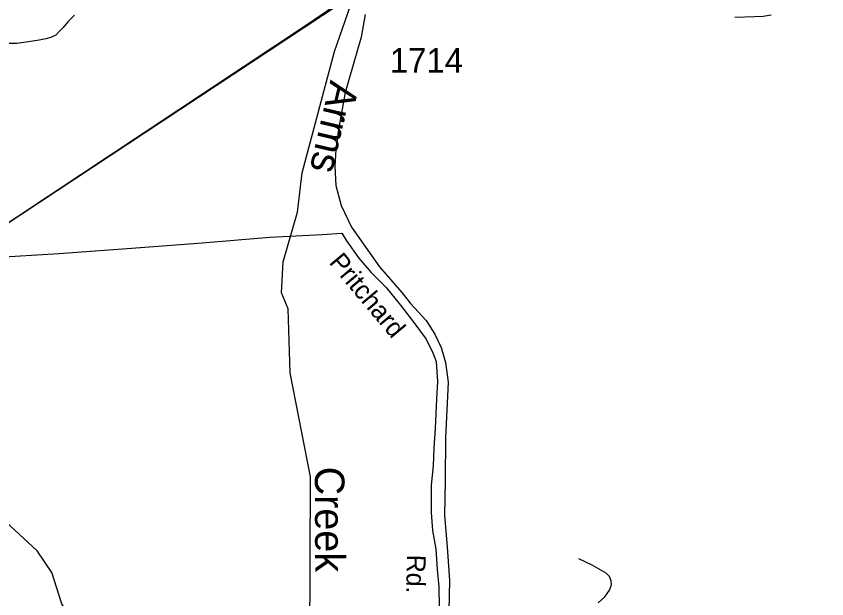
# Model space of a CAD drawing. Extents: x 2169602 to 2449496, y 721995 to 810662.
# Drawn here: x 2410109 to 2414228, y 779230 to 782189 of the extents above; entities that cross this region are included whole.
import ezdxf

# ---------------------------------------------------------------- set-up
doc = ezdxf.new("R2010")
doc.units = 0
doc.layers.add('Default', color=7, linetype='Continuous')

msp = doc.modelspace()

# ---------------------------------------------------------------- linework, layer by layer
at = {"layer": 'Default'}
for points in [[(2404733.3, 777630.1), (2405147.7, 777901.7), (2405686.5, 778256.1), (2406217, 778608.9), (2406723.1, 778942.9), (2406763.5, 778969.7), (2406882.8, 779048.4), (2407298.2, 779322.5), (2407781.8, 779645.4), (2408089.5, 779845.1), (2409777.7, 780948.3), (2417318.1, 785926.9), (2418416.8, 786689.4), (2419197, 787197.8), (2419206.4, 787204.1), (2419600.8, 787465.3), (2419633.6, 787486.8), (2420385.7, 787984.7)], [(2404733.3, 777630.1), (2405147.7, 777901.7), (2405686.5, 778256.1), (2406217, 778608.9), (2406723.1, 778942.9), (2406763.5, 778969.7), (2406882.8, 779048.4), (2407298.2, 779322.5), (2407781.8, 779645.4), (2408089.5, 779845.1), (2409777.7, 780948.3), (2417318.1, 785926.9), (2418416.8, 786689.4), (2419197, 787197.8), (2419206.4, 787204.1), (2419600.8, 787465.3), (2419633.6, 787486.8), (2420385.7, 787984.7)], [(2411333.8, 777641.8), (2411316.8, 777750.4), (2411240.7, 777876.6), (2411256.7, 778125.6), (2411346.7, 778350.1), (2411445.8, 778469.4), (2411493.8, 778793.2), (2411600.8, 779001), (2411604.7, 779850.5), (2411501.8, 780377.4), (2411491.7, 780702.4), (2411457.7, 780785.1), (2411464.9, 780942.4), (2411538.7, 781193.4), (2411562.7, 781393.1), (2411725.7, 782009.7), (2411807.7, 782244.2), (2411973.8, 782437.7), (2411972.8, 782519.7), (2411847.7, 782561.6), (2411805.9, 782611.6), (2411826.8, 783336.2), (2411864.7, 783994.8), (2411971.8, 784209.1)], [(2409777.7, 780948.3), (2411594.3, 782153), (2411820.3, 782308.1)], [(2410404.8, 782195.2), (2410371, 782160.9), (2410347.2, 782132.5), (2410328.9, 782112.5), (2410311.1, 782092.5), (2410285.2, 782080.6), (2410259.2, 782074.4), (2410225.4, 782068.1), (2410171.4, 782059.7), (2410111.8, 782051.3), (2410051.7, 782051)], [(2411882.7, 782197.4), (2411862, 782082.5), (2411780.7, 781801.2), (2411747.2, 781614), (2411733.6, 781512.1), (2411728.5, 781428.2), (2411733.6, 781328.8), (2411760.1, 781228.1), (2411813, 781117.1), (2411955, 780915.8), (2412067.9, 780786.7), (2412113.3, 780730.7), (2412191.8, 780643.5), (2412237, 780575.1), (2412267.9, 780506.6), (2412290.5, 780430.5), (2412303.4, 780331.1), (2412291.2, 780047.2), (2412287.9, 779831.6), (2412284.7, 779653.5), (2412299.6, 779493.5), (2412311.2, 779323.1), (2412307.9, 779170.8)], [(2413944.8, 782194.3), (2413903.8, 782187.4), (2413861, 782185.7), (2413760.9, 782182.3)], [(2409991.2, 780964.1), (2410326.5, 780984.8), (2410740.5, 781014.7), (2411054.7, 781037.6), (2411398, 781066.3), (2411663.5, 781079.9), (2411763.2, 781087.9), (2411787.7, 781048.6), (2411850, 780960.1), (2411912.7, 780887.7), (2411989.7, 780811.1), (2412061, 780721.4), (2412129, 780633.4), (2412192.2, 780548.2), (2412226.7, 780480.3), (2412242.5, 780435.6), (2412250.2, 780334.2), (2412244, 780245.7), (2412238.2, 780095.2), (2412230.7, 779995.3), (2412227, 779904.9)], [(2409991.2, 780964.1), (2410326.5, 780984.8), (2410740.5, 781014.7), (2411054.7, 781037.6), (2411398, 781066.3), (2411663.5, 781079.9), (2411763.2, 781087.9), (2411787.7, 781048.6), (2411850, 780960.1), (2411912.7, 780887.7), (2411989.7, 780811.1), (2412061, 780721.4), (2412129, 780633.4), (2412192.2, 780548.2), (2412226.7, 780480.3), (2412242.5, 780435.6), (2412250.2, 780334.2), (2412244, 780245.7), (2412238.2, 780095.2), (2412230.7, 779995.3), (2412227, 779904.9)], [(2411273.7, 776355.1), (2411223.6, 776461.1), (2411229.6, 776779.1), (2411262.6, 776935.9), (2411252.5, 777205.1), (2411065.5, 777845.3), (2410922.6, 778077.9), (2410953.6, 778461), (2410928.6, 778553.4), (2410861.5, 778626.9), (2410610.6, 778756.7), (2410341.7, 779205), (2410290.7, 779363.5), (2410215.6, 779473.3), (2410056.7, 779620.8), (2409930.6, 779803.9), (2409837.7, 780002.5), (2409422.1, 780716)], [(2412227, 779904.9), (2412217.5, 779807.6), (2412217.7, 779767.6), (2412218.2, 779668.4), (2412224.5, 779577.1), (2412241.7, 779481.8), (2412247.5, 779379), (2412257, 779291), (2412258, 779188.1)], [(2412227, 779904.9), (2412217.5, 779807.6), (2412217.7, 779767.6), (2412218.2, 779668.4), (2412224.5, 779577.1), (2412241.7, 779481.8), (2412247.5, 779379), (2412257, 779291), (2412258, 779188.1)], [(2413066.5, 779209.5), (2413100.7, 779240.3), (2413123.8, 779274.5), (2413134, 779301.9), (2413132.3, 779322.4), (2413123.8, 779342.9), (2413106.7, 779360), (2413034.8, 779401.1), (2412968.1, 779433.6)]]:
    msp.add_lwpolyline(points, dxfattribs=at)

# ---------------------------------------------------------------- texts
msp.add_text('1714', height=125, dxfattribs=at).set_placement((2412007.5, 781902.2))
for s, height, rotation, p in [('Arms', 150, 256.9197, (2411705.9, 781868.2)), ('Pritchard', 95, 309.9399, (2411694.7, 780937.1)), ('Creek', 150, 270.1904, (2411626.6, 779901.2)), ('Rd.', 95, 268.6199, (2412095.1, 779455.6))]:
    msp.add_text(s, height=height, rotation=rotation, dxfattribs=at).set_placement(p)

doc.saveas('drawing.dxf')
